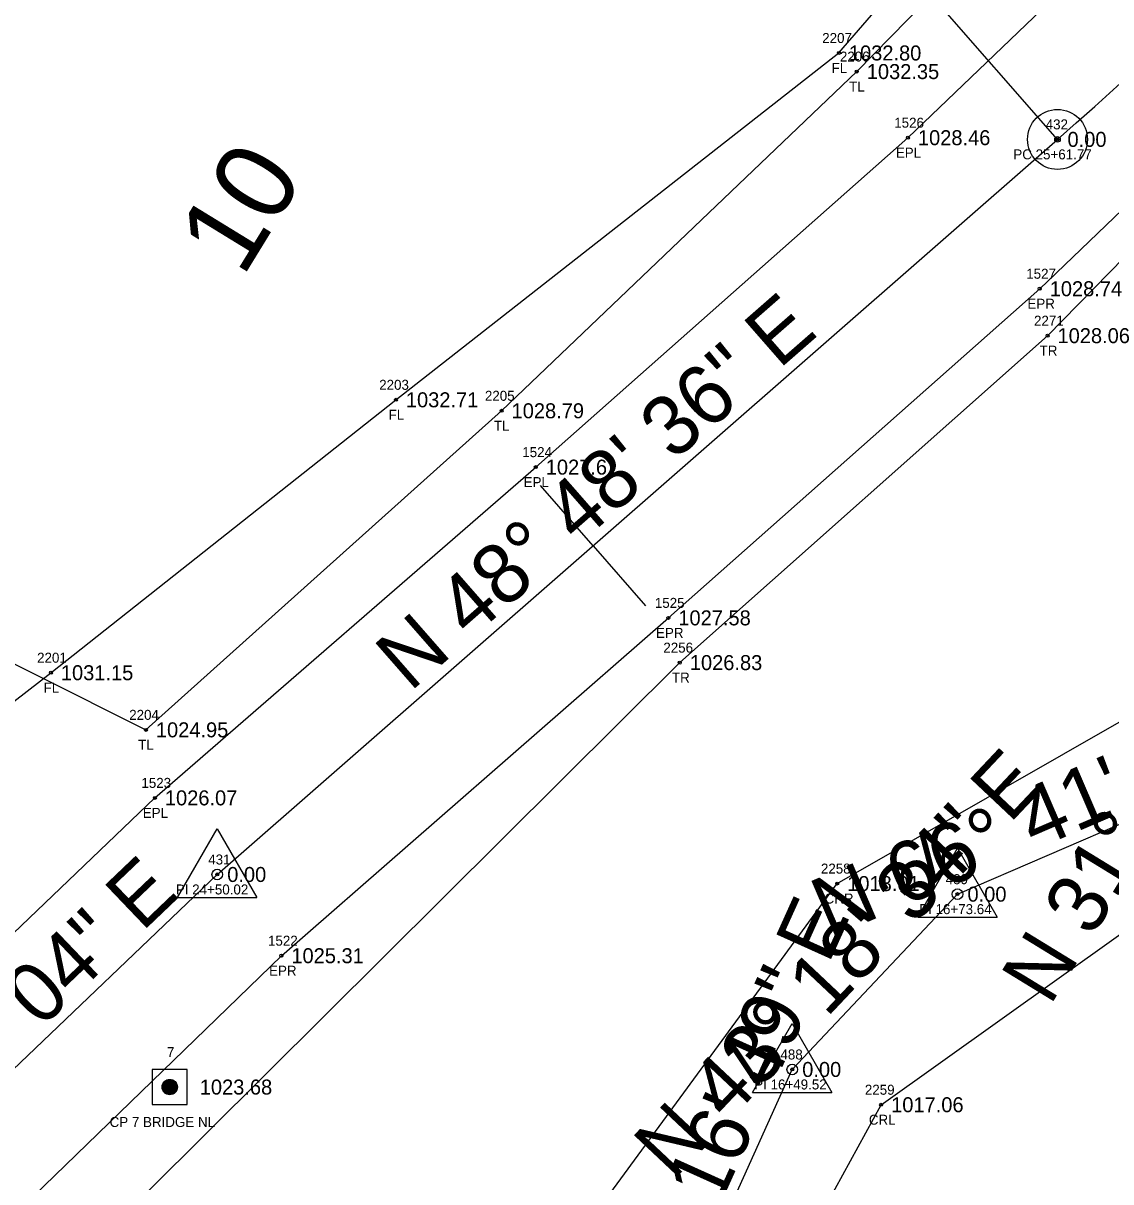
# Model space of a CAD drawing. Extents: x 1578957 to 1581675, y 1115963 to 1120391.
# Drawn here: x 1580189.7 to 1580298.5, y 1117709.5 to 1117825.5 of the extents above; entities that cross this region are included whole.
import ezdxf

# ---------------------------------------------------------------- set-up
doc = ezdxf.new("R2010")
doc.units = 0
for name, color, linetype in [('RD_EX_Fence_Other', 7, 'Continuous'), ('RD_EX_Fence_Other_txCode', 7, 'Continuous'), ('RD_EX_H2O', 7, 'Continuous'), ('RD_EX_H2O_txCode', 7, 'Continuous'), ('RD_EX_Road', 7, 'Continuous'), ('RD_EX_Road_txCode', 7, 'Continuous'), ('RD_EX_TX_Fence_Other_ELEV', 7, 'Continuous'), ('RD_EX_TX_H2O_ELEV', 7, 'Continuous'), ('RD_EX_TX_Road_ELEV', 7, 'Continuous'), ('RD_EX_TX_VEG_ELEV', 7, 'Continuous'), ('RD_EX_VEG', 7, 'Continuous'), ('RD_EX_VEG_txCode', 7, 'Continuous'), ('RD_HC_Cl', 7, 'Continuous'), ('RD_HC_Data', 7, 'Continuous'), ('RD_HC_Data_Tic', 7, 'Continuous'), ('RD_HC_Survey', 7, 'Continuous'), ('RD_HC_Survey_ELEV', 7, 'Continuous'), ('RD_HC_Survey_txCode', 7, 'Continuous'), ('RD_HC_TX_Sta50', 7, 'Continuous'), ('RD_HC_txCode', 7, 'Continuous'), ('RD_SMD_Locator', 7, 'Continuous')]:
    doc.layers.add(name, color=color, linetype=linetype)

msp = doc.modelspace()

# ---------------------------------------------------------------- linework, layer by layer
at = {"layer": 'RD_EX_Fence_Other'}
msp.add_lwpolyline([(1579823.1, 1118041.09), (1579819.64, 1117977.76), (1579811.21, 1117936.27), (1579806.91, 1117888.2), (1579805.65, 1117872.98), (1579810.22, 1117834.8), (1579821.35, 1117805.11), (1579835.23, 1117784.19), (1579851.4, 1117768.05), (1579868.55, 1117757.56), (1579908.33, 1117744.23), (1579949.73, 1117742.64), (1579998.85, 1117745.11), (1580033.64, 1117749.16), (1580057.08, 1117744.23), (1580092.08, 1117730.79), (1580117.52, 1117724.62), (1580141.72, 1117727.93), (1580159.98, 1117735.31), (1580192.44, 1117760.45), (1580226.97, 1117787.77), (1580271.31, 1117822.49), (1580302.1, 1117858.03)], dxfattribs=at)
at = {"layer": 'RD_EX_H2O'}
for points in [[(1580247.39, 1117706.92), (1580271.14, 1117739.34), (1580301.48, 1117756.69)], [(1580263.26, 1117694.77), (1580275.54, 1117717.2), (1580305.23, 1117738.37), (1580328.52, 1117709.87), (1580366.5, 1117704.64)]]:
    msp.add_lwpolyline(points, dxfattribs=at)
at = {"layer": 'RD_EX_Road'}
for points in [[(1580132.94, 1117689.89), (1580152.25, 1117701.26), (1580167.4, 1117714.02), (1580202.85, 1117747.92), (1580240.97, 1117781.03), (1580278.22, 1117814.01), (1580314.49, 1117848.76), (1580346.17, 1117886.72), (1580374.27, 1117928.33), (1580397.16, 1117972.42), (1580413.49, 1118019.66), (1580424.92, 1118067.62), (1580431.49, 1118116.98), (1580436.81, 1118166.42), (1580442.56, 1118216.33), (1580451.48, 1118265.26), (1580462.53, 1118314.08), (1580473.88, 1118362.54), (1580483.48, 1118411.51)], [(1580144.45, 1117641.55), (1580155.79, 1117665.53), (1580182, 1117699.63), (1580215.51, 1117732.12), (1580254.24, 1117765.94), (1580291.41, 1117798.89), (1580327.79, 1117833.81), (1580361.61, 1117873.47), (1580391.54, 1117917.75), (1580415.57, 1117964.64), (1580432.49, 1118014.02), (1580444.75, 1118063.23), (1580451.68, 1118114.82), (1580456.81, 1118164.4), (1580462.66, 1118213.64), (1580471.15, 1118260.76), (1580481.73, 1118308.53), (1580493.79, 1118358.47), (1580503.62, 1118407.2)]]:
    msp.add_lwpolyline(points, dxfattribs=at)
at = {"layer": 'RD_EX_VEG'}
for points in [[(1580229.39, 1117648.74), (1580165.31, 1117657.96), (1580190.27, 1117696.71), (1580255.39, 1117761.46), (1580292.19, 1117794.19), (1580369.26, 1117872.95), (1580397.16, 1117918.84), (1580418.33, 1117963.11), (1580437.18, 1118009.94), (1580450.07, 1118063.26), (1580457.12, 1118116.13), (1580460.93, 1118164.8), (1580467.23, 1118212.76), (1580476.46, 1118260.96), (1580485.08, 1118308.16), (1580501.94, 1118328.3), (1580585.89, 1118345.53)], [(1580087.69, 1117803.9), (1580148.66, 1117786.57), (1580180.04, 1117765.71), (1580201.95, 1117754.73), (1580237.55, 1117786.67), (1580273.1, 1117820.63), (1580306.94, 1117855.17), (1580338.22, 1117894.07), (1580365.76, 1117938.41), (1580387.11, 1117979.41), (1580401.63, 1118023.89), (1580405.64, 1118038.16), (1580418.87, 1118115.49), (1580427.53, 1118167.2), (1580431.61, 1118217.5), (1580441.36, 1118268.1), (1580453.33, 1118318.55), (1580411.81, 1118312.94), (1580376.62, 1118313.13)]]:
    msp.add_lwpolyline(points, dxfattribs=at)
at = {"layer": 'RD_HC_Cl'}
for p, q in [((1580209.09, 1117740.25), (1580293.19, 1117813.84)), ((1580283.18, 1117738.28), (1580306.74, 1117748.43)), ((1580164.51, 1117697.67), (1580209.09, 1117740.25)), ((1580266.64, 1117720.73), (1580283.18, 1117738.28)), ((1580258.28, 1117702.2), (1580266.64, 1117720.73))]:
    msp.add_line(p, q, dxfattribs=at)
msp.add_arc((1580009.48, 1118138.04), 430.81, 311.1901, 353.1039, dxfattribs=at)
at = {"layer": 'RD_HC_Data'}
for p, q in [((1580293.19, 1117813.84), (1580216.18, 1117901.84)), ((1580205.12, 1117737.95), (1580209.09, 1117744.83)), ((1580209.09, 1117744.83), (1580213.06, 1117737.95)), ((1580279.21, 1117735.99), (1580283.18, 1117742.87)), ((1580283.18, 1117742.87), (1580287.15, 1117735.99)), ((1580205.12, 1117737.95), (1580213.06, 1117737.95)), ((1580279.21, 1117735.99), (1580287.15, 1117735.99)), ((1580262.67, 1117718.44), (1580266.64, 1117725.32)), ((1580266.64, 1117725.32), (1580270.61, 1117718.44)), ((1580262.67, 1117718.44), (1580270.61, 1117718.44))]:
    msp.add_line(p, q, dxfattribs=at)
for centre, radius in [((1580293.19, 1117813.84), 3), ((1580293.19, 1117813.84), 0.282), ((1580209.09, 1117740.25), 0.529), ((1580283.18, 1117738.28), 0.529), ((1580266.64, 1117720.73), 0.529)]:
    msp.add_circle(centre, radius, dxfattribs=at)
at = {"layer": 'RD_HC_Data_Tic'}
for q in [(1580241.44, 1117779.18), (1580251.97, 1117767.14)]:
    msp.add_line((1580246.7, 1117773.16), q, dxfattribs=at)
at = {"layer": 'RD_HC_Survey'}
for p, q in [((1580203.77, 1117718.46), (1580203.77, 1117719.48)), ((1580203.79, 1117718.43), (1580203.79, 1117719.51)), ((1580203.82, 1117718.41), (1580203.82, 1117719.53)), ((1580203.84, 1117718.38), (1580203.84, 1117719.55)), ((1580203.86, 1117718.36), (1580203.86, 1117719.57)), ((1580203.89, 1117718.34), (1580203.89, 1117719.59)), ((1580203.91, 1117718.33), (1580203.91, 1117719.61)), ((1580203.94, 1117718.31), (1580203.94, 1117719.62)), ((1580203.96, 1117718.3), (1580203.96, 1117719.64)), ((1580203.99, 1117718.28), (1580203.99, 1117719.65)), ((1580204.01, 1117718.27), (1580204.01, 1117719.66)), ((1580204.04, 1117718.26), (1580204.04, 1117719.67)), ((1580204.06, 1117718.25), (1580204.06, 1117719.68)), ((1580204.09, 1117718.24), (1580204.09, 1117719.69)), ((1580204.11, 1117718.23), (1580204.11, 1117719.7)), ((1580204.14, 1117718.23), (1580204.14, 1117719.71)), ((1580204.16, 1117718.22), (1580204.16, 1117719.72)), ((1580204.19, 1117718.21), (1580204.19, 1117719.72)), ((1580204.21, 1117718.21), (1580204.21, 1117719.73)), ((1580204.24, 1117718.21), (1580204.24, 1117719.73)), ((1580204.26, 1117718.2), (1580204.26, 1117719.73)), ((1580204.29, 1117718.2), (1580204.29, 1117719.73)), ((1580204.31, 1117718.2), (1580204.31, 1117719.74)), ((1580204.34, 1117718.2), (1580204.34, 1117719.74)), ((1580204.36, 1117718.2), (1580204.36, 1117719.74)), ((1580204.38, 1117718.2), (1580204.38, 1117719.74)), ((1580204.41, 1117718.2), (1580204.41, 1117719.73)), ((1580204.43, 1117718.2), (1580204.43, 1117719.73)), ((1580204.46, 1117718.21), (1580204.46, 1117719.73)), ((1580204.48, 1117718.21), (1580204.48, 1117719.72)), ((1580204.51, 1117718.22), (1580204.51, 1117719.72)), ((1580204.53, 1117718.22), (1580204.53, 1117719.71)), ((1580204.56, 1117718.23), (1580204.56, 1117719.71)), ((1580204.58, 1117718.24), (1580204.58, 1117719.7)), ((1580204.61, 1117718.25), (1580204.61, 1117719.69)), ((1580204.63, 1117718.26), (1580204.63, 1117719.68)), ((1580204.66, 1117718.27), (1580204.66, 1117719.67)), ((1580204.68, 1117718.28), (1580204.68, 1117719.66)), ((1580204.71, 1117718.29), (1580204.71, 1117719.64)), ((1580204.73, 1117718.3), (1580204.73, 1117719.63)), ((1580204.76, 1117718.32), (1580204.76, 1117719.62)), ((1580204.78, 1117718.34), (1580204.78, 1117719.6)), ((1580204.81, 1117718.35), (1580204.81, 1117719.58)), ((1580204.83, 1117718.37), (1580204.83, 1117719.56)), ((1580204.85, 1117718.39), (1580204.85, 1117719.54)), ((1580204.88, 1117718.42), (1580204.88, 1117719.52)), ((1580204.9, 1117718.44), (1580204.9, 1117719.49)), ((1580204.93, 1117718.47), (1580204.93, 1117719.46)), ((1580203.59, 1117718.79), (1580203.59, 1117719.15)), ((1580203.62, 1117718.71), (1580203.62, 1117719.23)), ((1580203.64, 1117718.65), (1580203.64, 1117719.29)), ((1580203.67, 1117718.6), (1580203.67, 1117719.34)), ((1580203.69, 1117718.55), (1580203.69, 1117719.38)), ((1580203.72, 1117718.52), (1580203.72, 1117719.42)), ((1580203.74, 1117718.49), (1580203.74, 1117719.45)), ((1580204.95, 1117718.5), (1580204.95, 1117719.43)), ((1580204.98, 1117718.54), (1580204.98, 1117719.4)), ((1580205, 1117718.58), (1580205, 1117719.36)), ((1580205.03, 1117718.62), (1580205.03, 1117719.31)), ((1580205.05, 1117718.68), (1580205.05, 1117719.26)), ((1580205.08, 1117718.74), (1580205.08, 1117719.19)), ((1580205.1, 1117718.86), (1580205.1, 1117719.08))]:
    msp.add_line(p, q, dxfattribs=at)
msp.add_lwpolyline([(1580206.09, 1117720.72), (1580202.59, 1117720.72), (1580202.59, 1117717.22), (1580206.09, 1117717.22)], close=True, dxfattribs=at)
msp.add_circle((1580204.34, 1117718.97), 0.769, dxfattribs=at)
at = {"layer": 'RD_SMD_Locator'}
for centre in [(1580271.31, 1117822.49), (1580273.1, 1117820.63), (1580278.22, 1117814.01), (1580293.19, 1117813.84), (1580291.41, 1117798.89), (1580292.19, 1117794.19), (1580226.97, 1117787.77), (1580237.55, 1117786.67), (1580240.97, 1117781.03), (1580254.24, 1117765.94), (1580255.39, 1117761.46), (1580192.44, 1117760.45), (1580201.95, 1117754.73), (1580202.85, 1117747.92), (1580209.09, 1117740.25), (1580271.14, 1117739.34), (1580283.18, 1117738.28), (1580215.51, 1117732.12), (1580266.64, 1117720.73), (1580204.34, 1117718.97), (1580275.54, 1117717.2)]:
    msp.add_circle(centre, 0.15, dxfattribs=at)

# ---------------------------------------------------------------- texts
at = {"layer": 'RD_EX_Fence_Other_txCode'}
for s, p in [('2207', (1580269.64, 1117823.49)), ('FL', (1580270.58, 1117820.49)), ('2203', (1580225.3, 1117788.77)), ('FL', (1580226.24, 1117785.77)), ('2201', (1580191.06, 1117761.45)), ('FL', (1580191.71, 1117758.45))]:
    msp.add_text(s, height=1, dxfattribs=at).set_placement(p)
at = {"layer": 'RD_EX_H2O_txCode'}
for s, p in [('2258', (1580269.51, 1117740.34)), ('CRR', (1580269.88, 1117737.34)), ('2259', (1580273.91, 1117718.2)), ('CRL', (1580274.31, 1117715.2))]:
    msp.add_text(s, height=1, dxfattribs=at).set_placement(p)
at = {"layer": 'RD_EX_Road_txCode'}
for s, p in [('1526', (1580276.85, 1117815.01)), ('EPL', (1580277.01, 1117812.01)), ('1527', (1580290.06, 1117799.89)), ('EPR', (1580290.18, 1117796.89)), ('1524', (1580239.62, 1117782.03)), ('EPL', (1580239.76, 1117779.03)), ('1525', (1580252.89, 1117766.94)), ('EPR', (1580253.01, 1117763.94)), ('1523', (1580201.5, 1117748.92)), ('EPL', (1580201.64, 1117745.92)), ('1522', (1580214.17, 1117733.12)), ('EPR', (1580214.28, 1117730.12))]:
    msp.add_text(s, height=1, dxfattribs=at).set_placement(p)
at = {"layer": 'RD_EX_TX_Fence_Other_ELEV'}
for s, p in [('1032.80', (1580272.31, 1117821.74)), ('1032.71', (1580227.97, 1117787.02)), ('1031.15', (1580193.44, 1117759.7))]:
    msp.add_text(s, height=1.5, dxfattribs=at).set_placement(p)
at = {"layer": 'RD_EX_TX_H2O_ELEV'}
for s, p in [('1018.01', (1580272.14, 1117738.59)), ('1017.06', (1580276.54, 1117716.45))]:
    msp.add_text(s, height=1.5, dxfattribs=at).set_placement(p)
at = {"layer": 'RD_EX_TX_Road_ELEV'}
for s, p in [('1028.46', (1580279.22, 1117813.26)), ('1028.74', (1580292.41, 1117798.14)), ('1027.61', (1580241.97, 1117780.28)), ('1027.58', (1580255.24, 1117765.19)), ('1026.07', (1580203.85, 1117747.17)), ('1025.31', (1580216.51, 1117731.37))]:
    msp.add_text(s, height=1.5, dxfattribs=at).set_placement(p)
at = {"layer": 'RD_EX_TX_VEG_ELEV'}
for s, p in [('1032.35', (1580274.1, 1117819.88)), ('1028.06', (1580293.19, 1117793.44)), ('1028.79', (1580238.55, 1117785.92)), ('1026.83', (1580256.39, 1117760.71)), ('1024.95', (1580202.95, 1117753.98))]:
    msp.add_text(s, height=1.5, dxfattribs=at).set_placement(p)
at = {"layer": 'RD_EX_VEG_txCode'}
for s, p in [('2206', (1580271.41, 1117821.63)), ('TL', (1580272.33, 1117818.63)), ('2271', (1580290.84, 1117795.19)), ('TR', (1580291.4, 1117792.19)), ('2205', (1580235.88, 1117787.67)), ('TL', (1580236.78, 1117784.67)), ('2256', (1580253.74, 1117762.46)), ('TR', (1580254.6, 1117759.46)), ('2204', (1580200.28, 1117755.73)), ('TL', (1580201.18, 1117752.73))]:
    msp.add_text(s, height=1, dxfattribs=at).set_placement(p)
at = {"layer": 'RD_HC_Data'}
for s, rotation, p in [('N 48%%d 48\' 36" E', 41.1901, (1580228.39, 1117758.46)), ('N 31%%d 30\' 23" E', 58.4935, (1580292.44, 1117727.01)), ('N 66%%d 41\' 41" E', 23.3053, (1580270.33, 1117733.83)), ('N 43%%d 18\' 34" E', 46.6905, (1580254.72, 1117709.55)), ('N 46%%d 19\' 04" E', 43.6822, (1580166.07, 1117700.54)), ('N 24%%d 16\' 49" E', 65.7197, (1580250.08, 1117686.45))]:
    msp.add_text(s, height=6, rotation=rotation, dxfattribs=at).set_placement(p)
at = {"layer": 'RD_HC_Survey_ELEV'}
for s, p in [('0.00', (1580294.19, 1117813.09)), ('0.00', (1580210.09, 1117739.5)), ('0.00', (1580284.18, 1117737.53)), ('0.00', (1580267.64, 1117719.98)), ('1023.68', (1580207.34, 1117718.22))]:
    msp.add_text(s, height=1.5, dxfattribs=at).set_placement(p)
at = {"layer": 'RD_HC_Survey_txCode'}
for s, p in [('7', (1580204.06, 1117721.97)), ('CP 7 BRIDGE NL', (1580198.32, 1117714.97))]:
    msp.add_text(s, height=1, dxfattribs=at).set_placement(p)
at = {"layer": 'RD_HC_TX_Sta50'}
msp.add_text('10', height=8, rotation=58.4935, dxfattribs=at).set_placement((1580211.63, 1117799.93))
at = {"layer": 'RD_HC_txCode'}
for s, p in [('432', (1580292.01, 1117814.84)), ('PC 25+61.77', (1580288.77, 1117811.84)), ('431', (1580208.19, 1117741.25)), ('PI 24+50.02', (1580204.95, 1117738.25)), ('489', (1580282, 1117739.28)), ('PI 16+73.64', (1580279.35, 1117736.28)), ('488', (1580265.46, 1117721.73)), ('PI 16+49.52', (1580262.84, 1117718.73))]:
    msp.add_text(s, height=1, dxfattribs=at).set_placement(p)

doc.saveas('drawing.dxf')
